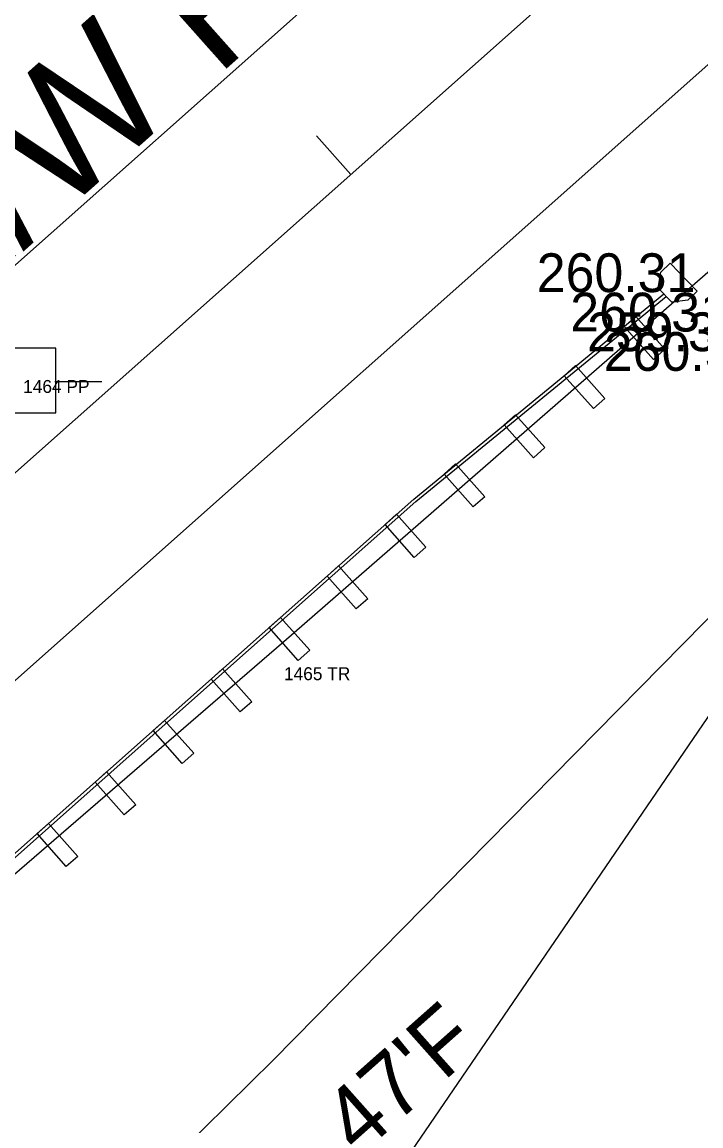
# Model space of a CAD drawing. Extents: x 49683 to 58852, y 49525 to 54803.
# Drawn here: x 55459 to 55511.5, y 53162.4 to 53247.8 of the extents above; entities that cross this region are included whole.
import ezdxf

# ---------------------------------------------------------------- set-up
doc = ezdxf.new("R2010")
doc.units = 0
for name, color, linetype in [('Level 11', 7, 'Continuous'), ('Level 13', 7, 'Continuous'), ('Level 18', 7, 'Continuous'), ('Level 19', 7, 'Continuous'), ('Level 20', 7, 'Continuous'), ('Level 25', 7, 'Continuous'), ('Level 27', 7, 'Continuous'), ('Level 32', 7, 'Continuous'), ('Level 48', 7, 'Continuous'), ('Level 59', 7, 'Continuous'), ('Level 61', 7, 'Continuous'), ('Level 9', 7, 'Continuous')]:
    doc.layers.add(name, color=color, linetype=linetype)

# ---------------------------------------------------------------- blocks, each defined once
blk = doc.blocks.new('PP')
at = {"layer": 'Level 9'}
for p, q in [((2.526, 2.452), (-2.474, 2.452)), ((-2.474, 2.452), (-2.474, -2.548)), ((2.526, -2.548), (2.526, 2.452)), ((-5.905, -0.111), (-2.436, -0.111)), ((2.454, -0.111), (6.095, -0.111)), ((-2.474, -2.548), (2.526, -2.548))]:
    blk.add_line(p, q, dxfattribs=at)

msp = doc.modelspace()

# ---------------------------------------------------------------- linework, layer by layer
at = {"layer": 'Level 11'}
for p, q in [((55479.228, 53199.919), (55778.326, 53460.623)), ((55416.975, 53146.156), (55479.228, 53199.919))]:
    msp.add_line(p, q, dxfattribs=at)
at = {"layer": 'Level 13'}
msp.add_line((55429.014, 53202.87), (55556.507, 53316.197), dxfattribs=at)
at = {"layer": 'Level 18'}
for p, q in [((55478.405, 53167.515), (55513.537, 53203.251)), ((55487.675, 53158.401), (55516.312, 53200.37)), ((55442.646, 53132.484), (55478.405, 53167.515))]:
    msp.add_line(p, q, dxfattribs=at)
at = {"layer": 'Level 19'}
for p, q in [((54181.768, 52078.16), (56150.851, 53828.445)), ((55484.391, 53236.04), (55481.734, 53239.03))]:
    msp.add_line(p, q, dxfattribs=at)
at = {"layer": 'Level 20'}
for p, q in [((55390.953, 53169.04), (56142.879, 53837.415)), ((55400.369, 53145.299), (56158.823, 53819.476))]:
    msp.add_line(p, q, dxfattribs=at)
at = {"layer": 'Level 27'}
for p, q in [((55489.26, 53210.933), (55508.61, 53226.795)), ((55489.426, 53210.747), (55508.776, 53226.608)), ((55505.54, 53224.278), (55506.424, 53225.064)), ((55506.424, 53225.064), (55508.682, 53222.522)), ((55507.798, 53221.737), (55505.54, 53224.278)), ((55508.682, 53222.522), (55507.798, 53221.737)), ((55500.896, 53220.472), (55501.78, 53221.257)), ((55501.78, 53221.257), (55504.038, 53218.715)), ((55503.155, 53217.93), (55500.896, 53220.472)), ((55504.038, 53218.715), (55503.155, 53217.93)), ((55496.252, 53216.665), (55497.136, 53217.45)), ((55497.136, 53217.45), (55499.394, 53214.908)), ((55498.511, 53214.123), (55496.252, 53216.665)), ((55499.394, 53214.908), (55498.511, 53214.123)), ((55491.608, 53212.858), (55492.492, 53213.643)), ((55492.492, 53213.643), (55494.75, 53211.102)), ((55493.867, 53210.317), (55491.608, 53212.858)), ((55388.385, 53121.267), (55489.26, 53210.933)), ((55388.551, 53121.08), (55489.426, 53210.747)), ((55494.75, 53211.102), (55493.867, 53210.317)), ((55487.043, 53208.963), (55487.927, 53209.748)), ((55487.927, 53209.748), (55490.185, 53207.206)), ((55489.302, 53206.421), (55487.043, 53208.963)), ((55490.185, 53207.206), (55489.302, 53206.421)), ((55482.559, 53204.976), (55483.442, 53205.762)), ((55483.442, 53205.762), (55485.701, 53203.22)), ((55484.817, 53202.435), (55482.559, 53204.976)), ((55485.701, 53203.22), (55484.817, 53202.435)), ((55478.074, 53200.99), (55478.958, 53201.775)), ((55480.333, 53198.449), (55478.074, 53200.99)), ((55478.958, 53201.775), (55481.216, 53199.234)), ((55481.216, 53199.234), (55480.333, 53198.449)), ((55473.59, 53197.004), (55474.473, 53197.789)), ((55474.473, 53197.789), (55476.732, 53195.248)), ((55475.848, 53194.463), (55473.59, 53197.004)), ((55476.732, 53195.248), (55475.848, 53194.463)), ((55469.105, 53193.018), (55469.989, 53193.803)), ((55469.989, 53193.803), (55472.247, 53191.262)), ((55471.364, 53190.476), (55469.105, 53193.018)), ((55472.247, 53191.262), (55471.364, 53190.476)), ((55464.621, 53189.032), (55465.504, 53189.817)), ((55466.879, 53186.49), (55464.621, 53189.032)), ((55465.504, 53189.817), (55467.763, 53187.275)), ((55467.763, 53187.275), (55466.879, 53186.49)), ((55460.136, 53185.046), (55461.02, 53185.831)), ((55461.02, 53185.831), (55463.278, 53183.289)), ((55462.395, 53182.504), (55460.136, 53185.046)), ((55463.278, 53183.289), (55462.395, 53182.504))]:
    msp.add_line(p, q, dxfattribs=at)
msp.add_lwpolyline([(55510.455, 53226.322), (55509.215, 53226.163), (55508.171, 53227.24), (55508.366, 53228.474), (55509.084, 53229.171), (55511.173, 53227.018)], close=True, dxfattribs=at)

# ---------------------------------------------------------------- block references
at = {"layer": 'Level 9'}
msp.add_blockref('PP', (55459.059, 53220.138), dxfattribs=at)

# ---------------------------------------------------------------- texts
at = {"layer": 'Level 25'}
msp.add_text("33' R/W FILE # 408-B", height=10, rotation=41.63333, dxfattribs=at).set_placement((55435.961, 53209.714))
at = {"layer": 'Level 32'}
for s, p in [('260.31', (55498.772, 53226.939)), ('260.31', (55501.364, 53223.892)), ('259.31', (55502.66, 53222.369)), ('260.31', (55503.956, 53220.846))]:
    msp.add_text(s, height=3, dxfattribs=at).set_placement(p)
at = {"layer": 'Level 48'}
msp.add_text("47'F", height=5, rotation=41.63339, dxfattribs=at).set_placement((55485.048, 53160.041))
at = {"layer": 'Level 59'}
msp.add_text('1464 PP', height=1, dxfattribs=at).set_placement((55459.059, 53219.138))
at = {"layer": 'Level 61'}
msp.add_text('1465 TR', height=1, dxfattribs=at).set_placement((55479.229, 53196.919))

doc.saveas('drawing.dxf')
